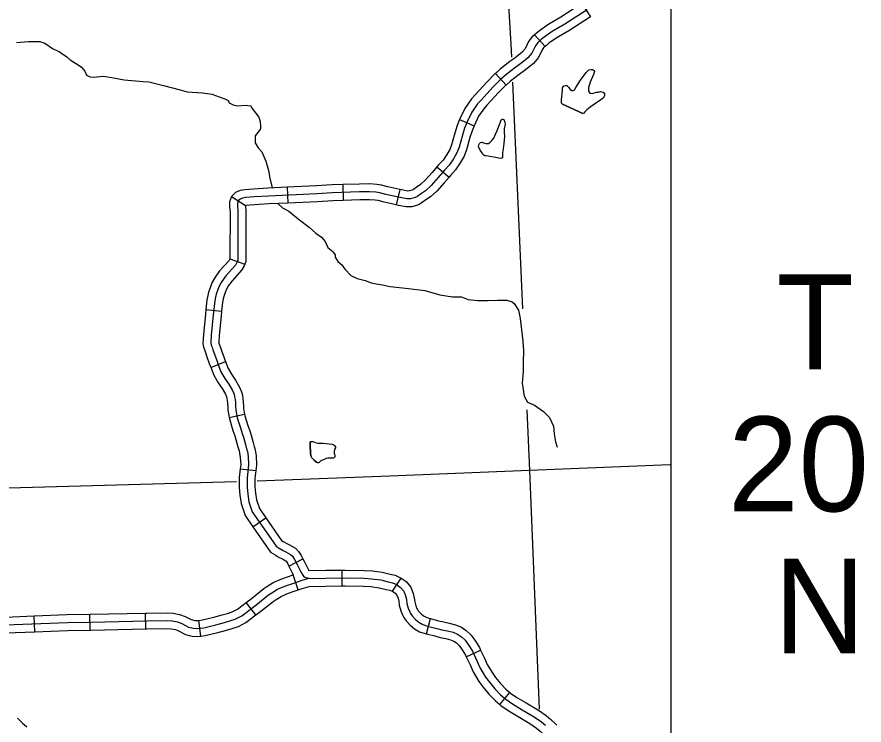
# Model space of a CAD drawing. Extents: x -5566 to 1759129, y -3726 to 731467.
# Drawn here: x -4493.8 to -4432.7, y 386.9 to 438 of the extents above; entities that cross this region are included whole.
import ezdxf

# ---------------------------------------------------------------- set-up
doc = ezdxf.new("R2010")
doc.units = 0
doc.layers.add('Default', color=7, linetype='Continuous')
doc.layers.add('R_No Plot', color=7, linetype='Continuous')

msp = doc.modelspace()

# ---------------------------------------------------------------- linework, layer by layer
at = {"layer": 'Default'}
for p, q in [((-4453.005, 438.953), (-4452.391, 437.994)), ((-4456.428, 436.704), (-4455.668, 435.855)), ((-4459.242, 433.922), (-4458.474, 433.081)), ((-4461.832, 430.585), (-4460.779, 430.149)), ((-4463.467, 427.178), (-4462.596, 426.443)), ((-4474.274, 425.704), (-4474.224, 424.566)), ((-4470.262, 425.896), (-4470.226, 424.758)), ((-4466.155, 425.548), (-4466.398, 424.435)), ((-4478.29, 425.044), (-4477.289, 424.388)), ((-4478.403, 420.542), (-4477.333, 420.153)), ((-4480.129, 416.893), (-4478.997, 416.772)), ((-4479.776, 412.714), (-4478.715, 413.13)), ((-4478.458, 409.103), (-4477.345, 409.345)), ((-4477.658, 405.404), (-4476.528, 405.263)), ((-4476.74, 401.213), (-4475.805, 401.863)), ((-4474.145, 398.381), (-4473.13, 398.899)), ((-4470.303, 396.953), (-4470.316, 398.092)), ((-4473.481, 396.666), (-4473.832, 397.75)), ((-4466.681, 396.558), (-4466.043, 397.502)), ((-4476.537, 394.85), (-4477.223, 395.76)), ((-4492.472, 393.644), (-4492.516, 394.783)), ((-4488.476, 393.766), (-4488.497, 394.905)), ((-4484.466, 393.851), (-4484.49, 394.99)), ((-4480.503, 393.328), (-4480.637, 394.459)), ((-4464.22, 393.482), (-4463.944, 394.587)), ((-4461.354, 391.838), (-4460.322, 392.318)), ((-4458.936, 388.388), (-4458.204, 389.261))]:
    msp.add_line(p, q, dxfattribs=at)
for points in [[(-4458.679, 445.274), (-4458.138, 436.027), (-4458.097, 435.096)], [(-4453.005, 438.953), (-4454.539, 437.97), (-4455.477, 437.43), (-4456.078, 436.998), (-4456.308, 436.811), (-4456.428, 436.704)], [(-4452.631, 438.516), (-4454.243, 437.484), (-4455.167, 436.951), (-4455.732, 436.545), (-4455.939, 436.377), (-4456.196, 436.147), (-4456.37, 435.92), (-4456.624, 435.376), (-4456.906, 435.055), (-4457.114, 434.887), (-4457.505, 434.568), (-4457.884, 434.31), (-4458.532, 433.799), (-4458.914, 433.45), (-4459.434, 432.928), (-4460.282, 432.001), (-4460.54, 431.719), (-4460.955, 431.113), (-4461.284, 430.419), (-4461.472, 429.964), (-4461.636, 429.455), (-4461.871, 428.593), (-4462.028, 428.194), (-4462.271, 427.763), (-4462.584, 427.308), (-4462.921, 426.941), (-4463.372, 426.407), (-4463.892, 425.835), (-4464.291, 425.459), (-4464.581, 425.263), (-4464.855, 425.075), (-4465.027, 424.966), (-4465.372, 424.872), (-4465.631, 424.864), (-4466.124, 424.958), (-4467.143, 425.181), (-4467.58, 425.303), (-4467.87, 425.35), (-4468.325, 425.373), (-4469.045, 425.365), (-4471.003, 425.303), (-4472.123, 425.229), (-4475.624, 425.075), (-4476.657, 425.004), (-4477.254, 424.961), (-4477.503, 424.922), (-4477.668, 424.847), (-4477.801, 424.722), (-4477.864, 424.55), (-4477.861, 424.4), (-4477.824, 423.899), (-4477.832, 420.734), (-4477.832, 420.445), (-4477.895, 420.273), (-4477.997, 420.093), (-4478.698, 419.317), (-4478.976, 418.918), (-4479.179, 418.565), (-4479.273, 418.322), (-4479.391, 417.985), (-4479.446, 417.77), (-4479.492, 417.502), (-4479.598, 416.501), (-4479.747, 415.048), (-4479.774, 414.483), (-4479.743, 414.323), (-4479.692, 414.17), (-4479.63, 413.97), (-4479.524, 413.657), (-4479.355, 413.203), (-4479.221, 412.859), (-4479.054, 412.399), (-4478.772, 411.913), (-4478.482, 411.49), (-4478.216, 411.04), (-4478.106, 410.774), (-4478.059, 410.578), (-4478.024, 410.386), (-4478.008, 410.174), (-4477.993, 409.888), (-4477.985, 409.685), (-4477.926, 409.34), (-4477.867, 409.07)], [(-4452.391, 437.994), (-4453.947, 436.997), (-4454.858, 436.472), (-4455.386, 436.092), (-4455.569, 435.944), (-4455.668, 435.855)], [(-4456.428, 436.704), (-4456.616, 436.536), (-4456.86, 436.217), (-4457.106, 435.691), (-4457.302, 435.467), (-4457.473, 435.329), (-4457.846, 435.025), (-4458.221, 434.769), (-4458.901, 434.234), (-4459.242, 433.922)], [(-4493.804, 436.139), (-4492.919, 436.232), (-4492.107, 436.223), (-4491.761, 436.106), (-4491.193, 435.722), (-4490.683, 435.474), (-4490.176, 435.111), (-4489.925, 434.899), (-4489.358, 434.546), (-4489.105, 434.363), (-4488.866, 434.076), (-4488.735, 433.789), (-4488.484, 433.682), (-4488.245, 433.658), (-4487.539, 433.73), (-4486.93, 433.634), (-4486.021, 433.455), (-4484.659, 433.335), (-4484.252, 433.323), (-4483.194, 433.047), (-4481.999, 432.747), (-4481.475, 432.593), (-4480.372, 432.518), (-4479.71, 432.414), (-4479.171, 432.234), (-4478.757, 432.097), (-4478.526, 431.972), (-4478.455, 431.792), (-4478.168, 431.642), (-4477.847, 431.585), (-4477.307, 431.637), (-4476.908, 431.588), (-4476.802, 431.386), (-4476.315, 430.764), (-4476.208, 430.453), (-4476.184, 430.118), (-4476.196, 429.915), (-4476.396, 429.656), (-4476.585, 429.428), (-4476.59, 429.233), (-4476.59, 428.922), (-4476.363, 428.54), (-4476.109, 428.268), (-4475.803, 427.578), (-4475.629, 426.909), (-4475.518, 426.371)], [(-4455.668, 435.855), (-4455.776, 435.758), (-4455.88, 435.623), (-4456.143, 435.061), (-4456.51, 434.642), (-4456.755, 434.445), (-4457.164, 434.111), (-4457.547, 433.85), (-4458.163, 433.365), (-4458.474, 433.081)], [(-4459.242, 433.922), (-4459.308, 433.861), (-4459.846, 433.321), (-4460.702, 432.386), (-4460.987, 432.074), (-4461.45, 431.397), (-4461.805, 430.65), (-4461.832, 430.585)], [(-4453.456, 432.905), (-4453.109, 433.438), (-4452.703, 433.988), (-4452.5, 434.174), (-4452.364, 434.208), (-4452.246, 434.191), (-4452.136, 434.132), (-4452.102, 434.055), (-4452.17, 433.852), (-4452.407, 433.285), (-4452.525, 432.888), (-4452.525, 432.634), (-4452.432, 432.49), (-4452.263, 432.465), (-4451.967, 432.566), (-4451.823, 432.575), (-4451.679, 432.608), (-4451.485, 432.575), (-4451.392, 432.49), (-4451.383, 432.338), (-4451.442, 432.168), (-4451.654, 432.016), (-4452.094, 431.703)], [(-4458.018, 433.286), (-4457.301, 416.943)], [(-4458.474, 433.081), (-4458.52, 433.038), (-4459.022, 432.535), (-4459.861, 431.617), (-4460.093, 431.364), (-4460.459, 430.828), (-4460.763, 430.188), (-4460.779, 430.149)], [(-4452.094, 431.703), (-4452.424, 431.474), (-4452.652, 431.288), (-4452.796, 431.136), (-4452.88, 431.051), (-4452.948, 431.017), (-4454.42, 431.694), (-4454.479, 431.762), (-4454.488, 432.008), (-4454.412, 432.693), (-4454.412, 432.879), (-4454.31, 433.023), (-4454.225, 433.048), (-4454.107, 433.048), (-4453.963, 432.896), (-4453.853, 432.769), (-4453.743, 432.685), (-4453.633, 432.685), (-4453.549, 432.744), (-4453.456, 432.905)], [(-4454.42, 431.694), (-4452.948, 431.017)], [(-4461.832, 430.585), (-4462.007, 430.161), (-4462.182, 429.617), (-4462.413, 428.773), (-4462.544, 428.439), (-4462.754, 428.065), (-4463.03, 427.664), (-4463.349, 427.318), (-4463.467, 427.178)], [(-4460.341, 428.386), (-4460.403, 428.494), (-4460.457, 428.563), (-4460.465, 428.633), (-4460.442, 428.771), (-4460.388, 428.872), (-4460.318, 428.926), (-4460.241, 428.956), (-4460.21, 428.956), (-4460.11, 428.918), (-4459.949, 428.872), (-4459.856, 428.864), (-4459.756, 428.872), (-4459.617, 428.949), (-4459.509, 429.072), (-4459.371, 429.257), (-4459.255, 429.527), (-4459.116, 429.804), (-4458.955, 430.236), (-4458.893, 430.436), (-4458.839, 430.567), (-4458.77, 430.614), (-4458.708, 430.629), (-4458.639, 430.59), (-4458.562, 430.405), (-4458.554, 430.259), (-4458.608, 429.92), (-4458.608, 429.689), (-4458.592, 429.373)], [(-4460.779, 430.149), (-4460.937, 429.768), (-4461.09, 429.292), (-4461.33, 428.414), (-4461.512, 427.949), (-4461.787, 427.461), (-4462.138, 426.952), (-4462.494, 426.565), (-4462.596, 426.443)], [(-4458.592, 429.373), (-4458.646, 428.864), (-4458.693, 428.471), (-4458.731, 428.193), (-4458.731, 427.993), (-4458.739, 427.877), (-4458.793, 427.808), (-4458.916, 427.792), (-4459.24, 427.854), (-4459.509, 427.9), (-4459.918, 427.962), (-4460.01, 427.962), (-4460.133, 428.039), (-4460.234, 428.209), (-4460.341, 428.386)], [(-4463.467, 427.178), (-4463.801, 426.782), (-4464.298, 426.235), (-4464.648, 425.906), (-4464.902, 425.734), (-4465.169, 425.551), (-4465.261, 425.493), (-4465.457, 425.439), (-4465.585, 425.435), (-4466.01, 425.516), (-4466.155, 425.548)], [(-4475.518, 426.371), (-4475.357, 425.657)], [(-4466.155, 425.548), (-4467.006, 425.734), (-4467.458, 425.86), (-4467.81, 425.917), (-4468.313, 425.943), (-4469.057, 425.935), (-4470.262, 425.896)], [(-4462.596, 426.443), (-4462.944, 426.031), (-4463.485, 425.436), (-4463.934, 425.013), (-4464.261, 424.793), (-4464.541, 424.6), (-4464.794, 424.439), (-4465.287, 424.304), (-4465.676, 424.293), (-4466.238, 424.4), (-4466.398, 424.435)], [(-4474.274, 425.704), (-4475.656, 425.643), (-4476.697, 425.572), (-4477.319, 425.527), (-4477.667, 425.472), (-4477.989, 425.328), (-4478.29, 425.044), (-4478.435, 424.645), (-4478.43, 424.374), (-4478.425, 424.308)], [(-4470.262, 425.896), (-4471.031, 425.872), (-4472.154, 425.798), (-4474.274, 425.704)], [(-4470.226, 424.758), (-4470.975, 424.734), (-4472.092, 424.661), (-4474.224, 424.566)], [(-4466.398, 424.435), (-4467.28, 424.628), (-4467.702, 424.745), (-4467.931, 424.782), (-4468.336, 424.803), (-4469.033, 424.796), (-4470.226, 424.758)], [(-4478.425, 424.308), (-4478.394, 423.88), (-4478.402, 420.735), (-4478.402, 420.546), (-4478.403, 420.542)], [(-4477.289, 424.388), (-4477.255, 423.919), (-4477.263, 420.734), (-4477.263, 420.345), (-4477.333, 420.153)], [(-4474.224, 424.566), (-4475.592, 424.506), (-4476.618, 424.436), (-4477.289, 424.388)], [(-4474.941, 424.535), (-4474.613, 424.213), (-4474.156, 423.975), (-4473.475, 423.42), (-4472.695, 422.818), (-4472.193, 422.403), (-4471.787, 422.108), (-4471.532, 421.79), (-4471.35, 421.363), (-4470.975, 421.064), (-4470.974, 421.057), (-4470.814, 420.834), (-4470.808, 420.659), (-4470.615, 420.361), (-4470.333, 420.112), (-4470.077, 419.763), (-4469.682, 419.35), (-4469.211, 419.123), (-4468.644, 418.976), (-4468.205, 418.817), (-4467.861, 418.738), (-4467.388, 418.671), (-4466.837, 418.546), (-4465.518, 418.403), (-4464.336, 418.247), (-4463.262, 417.943), (-4462.353, 417.801), (-4461.708, 417.794), (-4461.208, 417.621), (-4460.545, 417.546), (-4459.762, 417.528), (-4459.088, 417.568), (-4458.42, 417.569), (-4458.043, 417.438), (-4457.895, 417.321), (-4457.589, 416.852), (-4457.468, 416.232), (-4457.272, 414.608), (-4457.232, 413.916), (-4457.239, 413.077), (-4457.244, 412.383), (-4457.314, 411.573), (-4457.181, 410.633), (-4456.945, 410.214), (-4456.429, 409.997), (-4455.774, 409.54), (-4455.348, 409.098), (-4455.068, 408.476), (-4455.002, 407.914), (-4454.912, 407.338), (-4454.799, 406.946)], [(-4478.403, 420.542), (-4478.414, 420.512), (-4478.462, 420.428), (-4479.144, 419.672), (-4479.457, 419.223), (-4479.695, 418.812), (-4479.808, 418.519), (-4479.937, 418.149), (-4480.003, 417.889), (-4480.056, 417.581), (-4480.129, 416.893)], [(-4477.333, 420.153), (-4477.376, 420.034), (-4477.532, 419.758), (-4478.251, 418.962), (-4478.494, 418.612), (-4478.664, 418.318), (-4478.739, 418.125), (-4478.845, 417.821), (-4478.888, 417.651), (-4478.927, 417.424), (-4478.997, 416.772)], [(-4480.129, 416.893), (-4480.165, 416.56), (-4480.315, 415.09), (-4480.347, 414.442), (-4480.295, 414.177), (-4480.234, 413.995), (-4480.171, 413.794), (-4480.061, 413.467), (-4479.888, 413), (-4479.776, 412.714)], [(-4478.997, 416.772), (-4479.032, 416.442), (-4479.179, 415.005), (-4479.202, 414.524), (-4479.191, 414.468), (-4479.15, 414.345), (-4479.088, 414.146), (-4478.987, 413.847), (-4478.823, 413.405), (-4478.715, 413.13)], [(-4478.715, 413.13), (-4478.688, 413.06), (-4478.536, 412.641), (-4478.29, 412.218), (-4478.001, 411.796), (-4477.706, 411.294), (-4477.563, 410.95), (-4477.502, 410.696), (-4477.458, 410.458), (-4477.44, 410.211), (-4477.424, 409.915), (-4477.417, 409.744), (-4477.367, 409.448), (-4477.345, 409.345)], [(-4479.776, 412.714), (-4479.754, 412.658), (-4479.572, 412.157), (-4479.254, 411.609), (-4478.963, 411.184), (-4478.727, 410.785), (-4478.65, 410.597), (-4478.617, 410.46), (-4478.59, 410.313), (-4478.577, 410.138), (-4478.562, 409.862), (-4478.553, 409.626), (-4478.486, 409.231), (-4478.458, 409.103)], [(-4456.982, 409.661), (-4456.789, 405.276)], [(-4478.458, 409.103), (-4478.419, 408.925), (-4478.186, 408.163), (-4478.048, 407.771), (-4477.969, 407.514), (-4477.829, 406.984), (-4477.743, 406.697), (-4477.702, 406.534), (-4477.651, 406.215), (-4477.621, 405.703), (-4477.658, 405.404)], [(-4477.867, 409.07), (-4477.644, 408.34), (-4477.507, 407.949), (-4477.421, 407.671), (-4477.28, 407.138), (-4477.194, 406.848), (-4477.143, 406.649), (-4477.084, 406.276), (-4477.049, 405.685), (-4477.167, 404.736), (-4477.166, 404.081), (-4477.117, 403.557), (-4477.029, 403.019), (-4476.794, 402.288), (-4475.068, 399.804), (-4474.852, 399.675), (-4474.566, 399.499), (-4474.359, 399.397), (-4474.026, 399.221), (-4473.893, 399.084), (-4473.752, 398.864), (-4473.56, 398.488), (-4473.321, 398.003), (-4473.196, 397.791), (-4473.085, 397.647)], [(-4477.345, 409.345), (-4477.316, 409.214), (-4477.103, 408.518), (-4476.966, 408.128), (-4476.873, 407.828), (-4476.732, 407.292), (-4476.645, 407), (-4476.585, 406.764), (-4476.517, 406.338), (-4476.477, 405.667), (-4476.528, 405.263)], [(-4471.562, 406.098), (-4471.843, 405.96), (-4471.974, 405.853), (-4472.045, 405.835), (-4472.146, 405.877), (-4472.325, 406.014), (-4472.504, 406.199), (-4472.558, 406.324), (-4472.581, 406.551), (-4472.623, 407.105), (-4472.623, 407.296), (-4472.575, 407.355), (-4472.42, 407.355), (-4472.301, 407.319), (-4472.17, 407.266), (-4472.039, 407.242)], [(-4472.623, 407.296), (-4472.623, 407.105), (-4472.581, 406.551), (-4472.558, 406.324), (-4472.504, 406.199), (-4472.325, 406.014), (-4472.146, 405.877), (-4472.045, 405.835)], [(-4472.039, 407.242), (-4471.664, 407.236), (-4471.241, 407.2), (-4471.026, 407.182), (-4470.871, 407.093), (-4470.782, 406.992), (-4470.788, 406.92), (-4470.859, 406.795), (-4470.871, 406.646), (-4470.871, 406.503), (-4470.841, 406.384), (-4470.824, 406.312), (-4470.83, 406.241), (-4470.871, 406.205), (-4470.913, 406.157), (-4471.068, 406.169), (-4471.348, 406.169), (-4471.455, 406.151), (-4471.562, 406.098)], [(-4477.658, 405.404), (-4477.737, 404.771), (-4477.736, 404.054), (-4477.682, 403.484), (-4477.584, 402.885), (-4477.31, 402.033), (-4476.74, 401.213)], [(-4476.528, 405.263), (-4476.598, 404.701), (-4476.597, 404.108), (-4476.552, 403.63), (-4476.474, 403.153), (-4476.278, 402.543), (-4475.805, 401.863)], [(-4456.789, 405.276), (-4466.859, 404.857), (-4476.434, 404.499)], [(-4446.642, 405.677), (-4456.789, 405.276)], [(-4456.789, 405.276), (-4456.095, 388.064)], [(-4477.92, 404.451), (-4496.121, 403.941)], [(-4475.805, 401.863), (-4474.67, 400.23), (-4474.556, 400.162), (-4474.291, 399.998), (-4474.1, 399.905), (-4473.68, 399.682), (-4473.445, 399.44), (-4473.257, 399.148), (-4473.13, 398.899)], [(-4476.74, 401.213), (-4475.466, 399.379), (-4475.148, 399.189), (-4474.842, 399), (-4474.618, 398.89), (-4474.372, 398.76), (-4474.341, 398.728), (-4474.246, 398.58), (-4474.145, 398.381)], [(-4473.13, 398.899), (-4473.051, 398.743), (-4472.711, 398.053)], [(-4474.145, 398.381), (-4474.069, 398.233), (-4473.832, 397.75)], [(-4472.711, 398.053), (-4471.49, 398.078), (-4470.316, 398.092)], [(-4470.316, 398.092), (-4470.077, 398.094), (-4468.709, 398.07), (-4468.126, 398.029), (-4467.424, 397.937), (-4466.852, 397.804), (-4466.485, 397.712), (-4466.096, 397.538), (-4466.043, 397.502)], [(-4494.609, 394.132), (-4490.129, 394.305), (-4488.446, 394.336), (-4484.395, 394.422), (-4482.924, 394.443), (-4482.574, 394.418), (-4482.181, 394.344), (-4481.867, 394.226), (-4481.396, 393.982), (-4481.027, 393.888), (-4480.761, 393.871), (-4480.283, 393.927), (-4479.412, 394.132), (-4478.799, 394.304), (-4478.407, 394.422), (-4478.014, 394.548), (-4477.551, 394.799), (-4476.53, 395.569), (-4475.624, 396.295), (-4475.373, 396.459), (-4474.966, 396.702), (-4474.449, 396.929), (-4473.869, 397.133), (-4473.106, 397.38), (-4472.688, 397.504)], [(-4477.223, 395.76), (-4476.88, 396.019), (-4475.959, 396.756), (-4475.675, 396.942), (-4475.227, 397.209), (-4474.658, 397.459), (-4473.832, 397.75)], [(-4473.085, 397.647), (-4473.008, 397.587), (-4472.837, 397.539), (-4472.688, 397.504), (-4472.417, 397.489), (-4471.481, 397.509), (-4470.079, 397.525), (-4468.734, 397.501), (-4468.184, 397.462), (-4467.526, 397.376), (-4466.985, 397.25), (-4466.672, 397.172), (-4466.375, 397.039), (-4466.085, 396.843), (-4465.853, 396.559), (-4465.731, 396.236), (-4465.661, 395.956), (-4465.631, 395.677), (-4465.535, 395.34), (-4465.434, 395.083), (-4465.373, 394.952), (-4465.251, 394.786), (-4465.006, 394.524), (-4464.771, 394.331), (-4464.491, 394.165), (-4464.151, 394.052), (-4463.487, 393.886), (-4463.111, 393.79), (-4462.71, 393.702), (-4462.308, 393.606), (-4461.976, 393.467), (-4461.705, 393.283), (-4461.426, 393.03), (-4461.173, 392.654), (-4460.911, 392.235), (-4460.561, 391.484), (-4460.339, 391.002), (-4459.968, 390.374), (-4459.688, 389.998), (-4459.301, 389.52), (-4458.889, 389.092), (-4458.503, 388.768), (-4458.023, 388.429), (-4457.318, 388.017), (-4456.453, 387.497), (-4455.931, 387.142), (-4455.634, 386.894)], [(-4466.043, 397.502), (-4465.696, 397.268), (-4465.353, 396.847), (-4465.187, 396.406), (-4465.099, 396.057), (-4465.07, 395.787), (-4464.994, 395.522), (-4464.91, 395.307), (-4464.881, 395.244), (-4464.812, 395.15), (-4464.616, 394.941), (-4464.443, 394.8), (-4464.253, 394.686), (-4463.991, 394.599), (-4463.944, 394.587)], [(-4476.537, 394.85), (-4476.181, 395.119), (-4475.289, 395.833), (-4475.071, 395.976), (-4474.704, 396.195), (-4474.24, 396.399), (-4473.687, 396.593), (-4473.259, 396.732)], [(-4473.259, 396.732), (-4472.937, 396.836), (-4472.673, 396.914)], [(-4472.673, 396.914), (-4471.472, 396.939), (-4470.303, 396.953)], [(-4470.303, 396.953), (-4470.081, 396.955), (-4468.759, 396.932), (-4468.241, 396.895), (-4467.627, 396.815), (-4467.119, 396.697), (-4466.859, 396.632), (-4466.653, 396.539), (-4466.681, 396.559)], [(-4466.681, 396.558), (-4466.473, 396.418), (-4466.353, 396.271), (-4466.276, 396.065), (-4466.223, 395.856), (-4466.192, 395.567), (-4466.075, 395.158), (-4465.958, 394.859), (-4465.865, 394.66), (-4465.69, 394.421), (-4465.396, 394.107), (-4465.098, 393.863), (-4464.729, 393.644), (-4464.31, 393.505), (-4464.22, 393.482)], [(-4480.637, 394.459), (-4480.382, 394.489), (-4479.554, 394.683), (-4478.958, 394.851), (-4478.575, 394.966), (-4478.239, 395.074), (-4477.86, 395.279), (-4477.223, 395.76)], [(-4495.961, 394.701), (-4494.621, 394.701), (-4492.516, 394.783)], [(-4492.516, 394.783), (-4490.145, 394.874), (-4488.497, 394.905)], [(-4488.497, 394.905), (-4488.458, 394.905), (-4484.49, 394.99)], [(-4484.49, 394.99), (-4484.406, 394.992), (-4482.907, 395.013), (-4482.5, 394.984), (-4482.027, 394.894), (-4481.636, 394.747), (-4481.192, 394.518), (-4480.938, 394.453), (-4480.776, 394.443), (-4480.637, 394.459)], [(-4480.503, 393.328), (-4480.184, 393.366), (-4479.269, 393.58), (-4478.64, 393.757), (-4478.238, 393.878), (-4477.79, 394.022), (-4477.242, 394.319), (-4476.537, 394.85)], [(-4463.944, 394.587), (-4463.347, 394.438), (-4462.98, 394.344), (-4462.583, 394.258), (-4462.13, 394.149), (-4461.703, 393.97), (-4461.353, 393.732), (-4460.992, 393.405), (-4460.695, 392.964), (-4460.409, 392.507), (-4460.322, 392.318)], [(-4495.912, 393.562), (-4494.598, 393.562), (-4492.472, 393.644)], [(-4492.472, 393.644), (-4490.113, 393.736), (-4488.476, 393.766)], [(-4488.476, 393.766), (-4488.435, 393.766), (-4484.466, 393.851)], [(-4484.466, 393.851), (-4484.385, 393.853), (-4482.941, 393.874), (-4482.648, 393.852), (-4482.336, 393.793), (-4482.099, 393.704), (-4481.6, 393.447), (-4481.117, 393.323), (-4480.746, 393.299), (-4480.503, 393.328)], [(-4464.22, 393.482), (-4463.627, 393.334), (-4463.243, 393.235), (-4462.836, 393.147), (-4462.486, 393.063), (-4462.249, 392.963), (-4462.058, 392.834), (-4461.86, 392.654), (-4461.651, 392.344), (-4461.412, 391.963), (-4461.354, 391.838)], [(-4460.322, 392.318), (-4460.045, 391.723), (-4459.834, 391.267), (-4459.493, 390.69), (-4459.238, 390.348), (-4458.874, 389.897), (-4458.5, 389.509), (-4458.204, 389.261)], [(-4461.354, 391.838), (-4461.078, 391.244), (-4460.844, 390.737), (-4460.443, 390.058), (-4460.138, 389.649), (-4459.728, 389.142), (-4459.278, 388.675), (-4458.936, 388.388)], [(-4458.204, 389.261), (-4458.155, 389.22), (-4457.714, 388.908), (-4457.028, 388.507), (-4456.146, 387.977), (-4455.588, 387.598), (-4455.257, 387.321), (-4454.859, 386.949), (-4454.827, 386.909)], [(-4458.936, 388.388), (-4458.851, 388.317), (-4458.331, 387.95), (-4457.609, 387.527), (-4456.76, 387.017), (-4456.275, 386.687), (-4456.011, 386.467), (-4455.702, 386.178), (-4455.725, 386.208)], [(-4493.712, 387.4), (-4493.373, 387.05), (-4493.039, 386.774)]]:
    msp.add_lwpolyline(points, dxfattribs=at)
at = {"layer": 'R_No Plot'}
msp.add_lwpolyline([(-5018.988, 168.239), (-5018.988, 511.979), (-4446.603, 511.979), (-4446.603, 160.504), (-4913.433, 160.504)], dxfattribs=at)

# ---------------------------------------------------------------- texts
at = {"layer": 'Default'}
for s, height, p in [('T', 6.835, (-4438.968, 412.581)), ('20', 6.8348, (-4442.467, 402.329)), ('N', 6.835, (-4439.16, 392.077))]:
    msp.add_text(s, height=height, dxfattribs=at).set_placement(p)

doc.saveas('drawing.dxf')
